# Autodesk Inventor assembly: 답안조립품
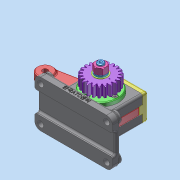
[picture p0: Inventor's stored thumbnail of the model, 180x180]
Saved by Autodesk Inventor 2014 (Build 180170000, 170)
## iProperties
Created: 2026-03
Part Number: 답안조립품
Document SubType Name: Assembly
Designer: dg
Author: dg
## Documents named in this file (15)
- C:\Users\dg\Desktop\660303V1005\답안조립품.iam
- C:\Users\dg\Desktop\660303V1005\가져온 구성요소\본체\본체.ipt
- C:\Users\dg\Desktop\660303V1005\가져온 구성요소\로드\로드.ipt
- C:\Users\dg\Desktop\660303V1005\가져온 구성요소\편심축\편심축.ipt
- C:\Users\dg\Desktop\660303V1005\가져온 구성요소\플랜지 오일레스 부시\플랜지 오일레스 부시.ipt
- C:\Users\dg\Desktop\660303V1005\가져온 구성요소\앞커버\앞커버.ipt
- C:\Users\dg\Desktop\660303V1005\가져온 구성요소\윗커버\윗커버.ipt
- C:\Users\dg\Desktop\660303V1005\가져온 구성요소\실링\실링.ipt
- C:\Users\dg\Desktop\660303V1005\가져온 구성요소\스프링와셔 M10\스프링와셔 M10.ipt
- C:\Users\dg\Desktop\660303V1005\가져온 구성요소\평와셔 M10\평와셔 M10.ipt
- C:\Users\dg\Desktop\660303V1005\가져온 구성요소\평행키 4x4x10\평행키 4x4x10.ipt
- C:\Users\dg\Desktop\660303V1005\가져온 구성요소\6각 구멍붙이 볼트 M4x10\6각 구멍붙이 볼트 M4x10.ipt
- C:\Users\dg\Desktop\660303V1005\가져온 구성요소\6각 너트 M10\6각 너트 M10.ipt
- C:\Users\dg\Desktop\660303V1005\가져온 구성요소\그리스 니플 M6x0.75\그리스 니플 M6x0.75.ipt
- C:\Users\dg\Desktop\660303V1005\가져온 구성요소\스퍼기어\스퍼기어.ipt
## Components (12 placed, 4 different names)
1. 플랜지 오일레스 부시:1
2. 플랜지 오일레스 부시:2
3. 6각 너트 M10:1
4. 그리스 니플 M6x0.75:1
5. 6각 구멍붙이 볼트 M4x10:1
6. 6각 구멍붙이 볼트 M4x10:2
7. 6각 구멍붙이 볼트 M4x10:3
8. 6각 구멍붙이 볼트 M4x10:4
9. 6각 구멍붙이 볼트 M4x10:5
10. 6각 구멍붙이 볼트 M4x10:6
11. 6각 구멍붙이 볼트 M4x10:7
12. 6각 구멍붙이 볼트 M4x10:8
